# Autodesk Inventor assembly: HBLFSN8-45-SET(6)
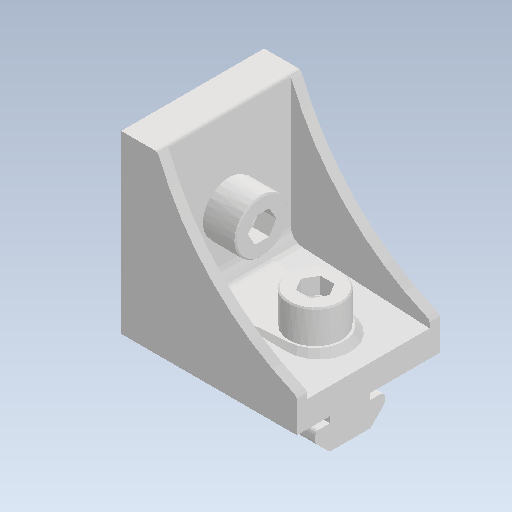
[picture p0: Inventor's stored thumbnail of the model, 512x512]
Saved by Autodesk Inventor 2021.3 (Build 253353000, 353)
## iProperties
Created: 2022-02
Part Number: HBLFSN8-45-SET(6)
Document SubType Name: Assembly
Designer: kengo
Author: kengo
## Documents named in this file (4)
- C:\Users\kengo\Documents\S2S_frame\SDC345\frame_misumi_ver12\HBLFSN8-45-SET(6).iam
- C:\Users\kengo\Documents\S2S_frame\SDC345\frame_misumi_ver12\HBLFSN8-45.ipt
- C:\Users\kengo\Documents\S2S_frame\SDC345\frame_misumi_ver12\HNTT8-8.ipt
- C:\Users\kengo\Documents\S2S_frame\SDC345\frame_misumi_ver12\CBM8-20.ipt
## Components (5 placed, 3 different names)
1. HBLFSN8-45
2. HNTT8-8
3. CBM8-20
4. HNTT8-8:1
5. CBM8-20:1
